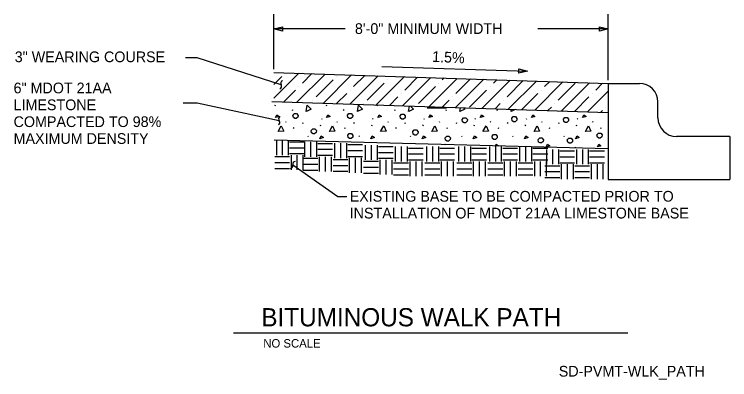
# Model space of a CAD drawing. Extents: x 9960.2 to 10030.1, y 10022.5 to 10058.1.
import ezdxf

# ---------------------------------------------------------------- set-up
doc = ezdxf.new("R2010")
doc.units = 0
for name, color, linetype in [('Default', 7, 'Continuous'), ('G-ANNO-TEXT', 7, 'Continuous'), ('G-ANNO-TTXT', 7, 'Continuous'), ('G-DETL-LINE', 7, 'Continuous'), ('G-DETL-OTLN', 7, 'Continuous'), ('G-DETL-PATT', 7, 'Continuous')]:
    doc.layers.add(name, color=color, linetype=linetype)

msp = doc.modelspace()

# ---------------------------------------------------------------- linework, layer by layer
at = {"layer": 'Default'}
for p, q in [((9997.025, 10052.061), (9997.037, 10052.073)), ((9994.36, 10049.396), (9994.36, 10049.396)), ((10018.234, 10042.898), (10018.234, 10041.987))]:
    msp.add_line(p, q, dxfattribs=at)
at = {"layer": 'G-ANNO-TEXT'}
for p, q in [((9985.587, 10052.756), (9985.587, 10058.112)), ((10018.229, 10051.69), (10018.229, 10058.112)), ((9992.55, 10056.685), (9985.587, 10056.685)), ((10018.229, 10056.685), (10011.359, 10056.685)), ((9996.134, 10053.035), (10010.341, 10052.567)), ((10000.549, 10048.997), (10002.434, 10048.997)), ((9981.617, 10027.034), (10020.141, 10027.034))]:
    msp.add_line(p, q, dxfattribs=at)
for points in [[(9986.42, 10056.477), (9985.587, 10056.685), (9986.42, 10056.893)], [(10017.395, 10056.893), (10018.229, 10056.685), (10017.395, 10056.477)], [(10009.515, 10052.802), (10010.341, 10052.567), (10009.501, 10052.386)]]:
    msp.add_lwpolyline(points, close=True, dxfattribs=at)
at = {"layer": 'G-ANNO-TTXT'}
for points in [[(9986.284, 10051.242), (9978.077, 10053.871), (9976.928, 10053.871)], [(9986.101, 10047.728), (9978.069, 10049.437), (9976.728, 10049.437)], [(9987.428, 10043.427), (9991.831, 10040.338), (9992.69, 10040.338)]]:
    msp.add_lwpolyline(points, dxfattribs=at)
for centre, start, end in [((9986.497, 10051.393), 109.10802, 215.36823), ((9986.072, 10051.091), 289.10802, 35.36823), ((9986.297, 10047.899), 114.85482, 221.11503), ((9986.297, 10047.899), 114.85482, 221.11503), ((9985.904, 10047.556), 294.85482, 41.11503), ((9985.904, 10047.556), 294.85482, 41.11503), ((9987.676, 10043.507), 91.81446, 198.07466), ((9987.676, 10043.507), 91.81446, 198.07466), ((9987.181, 10043.346), 271.81446, 18.07466), ((9987.181, 10043.346), 271.81446, 18.07466)]:
    msp.add_arc(centre, 0.26, start, end, dxfattribs=at)
at = {"layer": 'G-DETL-LINE'}
for p, q in [((9985.58, 10052.451), (10018.234, 10051.375)), ((9985.39, 10049.603), (10018.234, 10048.522)), ((10018.234, 10044.992), (9985.592, 10045.849))]:
    msp.add_line(p, q, dxfattribs=at)
at = {"layer": 'G-DETL-OTLN'}
for p, q in [((10018.234, 10051.375), (10021.277, 10051.375)), ((10018.234, 10051.375), (10018.234, 10046.843)), ((10023.086, 10048.005), (10023.086, 10049.566)), ((10018.234, 10046.843), (10018.234, 10041.986)), ((10030.097, 10046.196), (10024.896, 10046.196)), ((10030.097, 10046.196), (10030.097, 10041.987)), ((10018.234, 10041.987), (10030.097, 10041.987))]:
    msp.add_line(p, q, dxfattribs=at)
for centre, start, end in [((10021.277, 10049.566), 0, 90), ((10024.896, 10048.005), 180, 270)]:
    msp.add_arc(centre, 1.809, start, end, dxfattribs=at)
at = {"layer": 'G-DETL-PATT'}
for p, q in [((9985.58, 10049.944), (9988.006, 10052.371)), ((9986.697, 10052.394), (9986.697, 10052.394)), ((9987.83, 10049.529), (9990.587, 10052.286)), ((9988.363, 10051.395), (9989.296, 10052.328)), ((9990.41, 10049.444), (9993.167, 10052.201)), ((9992.99, 10049.359), (9995.747, 10052.116)), ((9993.36, 10051.062), (9994.457, 10052.158)), ((9985.58, 10051.277), (9986.364, 10052.061)), ((9989.696, 10050.062), (9991.361, 10051.728)), ((9991.694, 10052.061), (9991.694, 10052.061)), ((9994.693, 10049.729), (9996.359, 10051.395)), ((9995.571, 10049.274), (9998.327, 10052.031)), ((9996.692, 10051.728), (9996.692, 10051.728)), ((9998.151, 10049.189), (10000.908, 10051.946)), ((9998.358, 10050.728), (9999.618, 10051.988)), ((10000.731, 10049.104), (10003.488, 10051.861)), ((10001.689, 10051.395), (10001.689, 10051.395)), ((10002.022, 10051.728), (10002.198, 10051.903)), ((10003.312, 10049.019), (10006.068, 10051.776)), ((10003.355, 10050.395), (10004.778, 10051.818)), ((10005.892, 10048.934), (10008.649, 10051.691)), ((10007.02, 10051.395), (10007.358, 10051.733)), ((10008.352, 10050.062), (10009.939, 10051.648)), ((10008.472, 10048.849), (10011.229, 10051.606)), ((10011.052, 10048.764), (10013.809, 10051.521)), ((10012.017, 10051.062), (10012.519, 10051.563)), ((10013.35, 10049.729), (10015.015, 10051.395)), ((10013.633, 10048.679), (10016.389, 10051.436)), ((10017.014, 10050.728), (10017.68, 10051.393)), ((9986.54, 10049.572), (9987.697, 10050.728)), ((9988.03, 10051.062), (9988.03, 10051.062)), ((9993.027, 10050.728), (9993.027, 10050.728)), ((9999.69, 10049.396), (10001.356, 10051.062)), ((10004.688, 10049.063), (10006.353, 10050.728)), ((10006.686, 10051.062), (10006.686, 10051.062)), ((10011.684, 10050.728), (10011.684, 10050.728)), ((9991.7, 10049.402), (9992.694, 10050.395)), ((9996.861, 10049.232), (9997.691, 10050.062)), ((9998.024, 10050.395), (9998.024, 10050.395)), ((10003.022, 10050.062), (10003.022, 10050.062)), ((10009.762, 10048.807), (10011.351, 10050.395)), ((10014.923, 10048.637), (10016.348, 10050.062)), ((10016.213, 10048.594), (10018.234, 10050.615)), ((10016.681, 10050.395), (10016.681, 10050.395)), ((9985.702, 10049.197), (9985.747, 10049.297)), ((9989.362, 10049.729), (9989.362, 10049.729)), ((9990.702, 10049.197), (9990.747, 10049.297)), ((10002.021, 10049.062), (10002.689, 10049.729)), ((10007.182, 10048.892), (10007.686, 10049.396)), ((10008.019, 10049.729), (10008.019, 10049.729)), ((10013.016, 10049.396), (10013.016, 10049.396)), ((9987.389, 10048.741), (9987.434, 10048.841)), ((9992.389, 10048.741), (9992.434, 10048.841)), ((9995.702, 10049.197), (9995.731, 10049.263)), ((9997.389, 10048.741), (9997.434, 10048.841)), ((10002.389, 10048.741), (10002.434, 10048.841)), ((10007.389, 10048.741), (10007.434, 10048.841)), ((10012.343, 10048.722), (10012.683, 10049.063)), ((10017.503, 10048.552), (10017.681, 10048.729)), ((10018.014, 10049.063), (10018.014, 10049.063)), ((9990.215, 10047.954), (9990.26, 10047.887)), ((9995.215, 10047.954), (9995.26, 10047.887)), ((10000.215, 10047.954), (10000.26, 10047.887)), ((10005.215, 10047.954), (10005.26, 10047.887)), ((10010.215, 10047.954), (10010.26, 10047.887)), ((10015.215, 10047.954), (10015.26, 10047.887)), ((9986.71, 10047.671), (9986.755, 10047.605)), ((9988.399, 10047.454), (9988.444, 10047.554)), ((9990.131, 10047.222), (9990.176, 10047.322)), ((9991.71, 10047.671), (9991.755, 10047.605)), ((9993.399, 10047.454), (9993.444, 10047.554)), ((9995.131, 10047.222), (9995.176, 10047.322)), ((9996.71, 10047.671), (9996.755, 10047.605)), ((9998.399, 10047.454), (9998.444, 10047.554)), ((10000.131, 10047.222), (10000.176, 10047.322)), ((10001.71, 10047.671), (10001.755, 10047.605)), ((10003.399, 10047.454), (10003.444, 10047.554)), ((10005.131, 10047.222), (10005.176, 10047.322)), ((10006.71, 10047.671), (10006.755, 10047.605)), ((10008.399, 10047.454), (10008.444, 10047.554)), ((10010.131, 10047.222), (10010.176, 10047.322)), ((10011.71, 10047.671), (10011.755, 10047.605)), ((10013.399, 10047.454), (10013.444, 10047.554)), ((10015.131, 10047.222), (10015.176, 10047.322)), ((10016.71, 10047.671), (10016.755, 10047.605)), ((9987.5, 10046.967), (9987.545, 10047.067)), ((9992.5, 10046.967), (9992.545, 10047.067)), ((9997.5, 10046.967), (9997.545, 10047.067)), ((10002.5, 10046.967), (10002.545, 10047.067)), ((10007.5, 10046.967), (10007.545, 10047.067)), ((10012.5, 10046.967), (10012.545, 10047.067)), ((10017.5, 10046.967), (10017.545, 10047.067)), ((9985.817, 10045.813), (9985.817, 10044.365)), ((9986.396, 10045.813), (9986.396, 10044.365)), ((9986.975, 10045.813), (9986.975, 10044.365)), ((9988.888, 10046.256), (9988.932, 10046.19)), ((9993.888, 10046.256), (9993.932, 10046.19)), ((9998.888, 10046.256), (9998.932, 10046.19)), ((10003.888, 10046.256), (10003.932, 10046.19)), ((10008.888, 10046.256), (10008.932, 10046.19)), ((10013.888, 10046.256), (10013.932, 10046.19)), ((9987.109, 10045.678), (9988.557, 10045.678)), ((9987.109, 10045.099), (9988.557, 10045.099)), ((9988.575, 10045.659), (9988.575, 10044.211)), ((9989.154, 10045.659), (9989.154, 10044.211)), ((9989.733, 10045.659), (9989.733, 10044.211)), ((9989.867, 10045.524), (9991.315, 10045.524)), ((9991.508, 10045.535), (9991.508, 10044.087)), ((9992.087, 10045.535), (9992.087, 10044.087)), ((9992.666, 10045.535), (9992.666, 10044.087)), ((9992.8, 10045.4), (9994.248, 10045.4)), ((9994.501, 10045.357), (9994.501, 10043.909)), ((9995.08, 10045.357), (9995.08, 10043.909)), ((9995.659, 10045.357), (9995.659, 10043.909)), ((9995.793, 10045.222), (9997.241, 10045.222)), ((9997.422, 10045.202), (9997.422, 10043.755)), ((9998.001, 10045.202), (9998.001, 10043.755)), ((9998.58, 10045.202), (9998.58, 10043.755)), ((10000.483, 10045.202), (10000.483, 10043.755)), ((10001.062, 10045.202), (10001.062, 10043.755)), ((10001.641, 10045.202), (10001.641, 10043.755)), ((10003.617, 10045.202), (10003.617, 10043.755)), ((10004.196, 10045.202), (10004.196, 10043.755)), ((10004.775, 10045.202), (10004.775, 10043.755)), ((10006.631, 10045.202), (10006.631, 10043.755)), ((10007.211, 10045.202), (10007.211, 10043.755)), ((10007.79, 10045.202), (10007.79, 10043.755)), ((10009.58, 10045.202), (10009.58, 10043.755)), ((10010.159, 10045.202), (10010.159, 10043.755)), ((10010.738, 10045.202), (10010.738, 10043.755)), ((10015.01, 10045.192), (10015.021, 10045.092)), ((9987.109, 10044.52), (9988.557, 10044.52)), ((9989.867, 10044.945), (9991.315, 10044.945)), ((9992.8, 10044.821), (9994.248, 10044.821)), ((9995.793, 10044.643), (9997.241, 10044.643)), ((9998.714, 10045.068), (10000.162, 10045.068)), ((9998.714, 10044.489), (10000.162, 10044.489)), ((10001.775, 10045.068), (10003.223, 10045.068)), ((10001.775, 10044.489), (10003.223, 10044.489)), ((10004.909, 10045.068), (10006.357, 10045.068)), ((10004.909, 10044.489), (10006.357, 10044.489)), ((10007.924, 10045.068), (10009.371, 10045.068)), ((10007.924, 10044.489), (10009.371, 10044.489)), ((10010.872, 10045.068), (10012.32, 10045.068)), ((10010.872, 10044.489), (10012.32, 10044.489)), ((10012.204, 10044.928), (10012.204, 10043.48)), ((10012.783, 10044.928), (10012.783, 10043.48)), ((10013.362, 10044.928), (10013.362, 10043.48)), ((10013.496, 10044.793), (10014.944, 10044.793)), ((10015.126, 10044.928), (10015.126, 10043.48)), ((10015.705, 10044.928), (10015.705, 10043.48)), ((10016.284, 10044.928), (10016.284, 10043.48)), ((10016.418, 10044.793), (10017.866, 10044.793)), ((9985.661, 10044.23), (9987.109, 10044.23)), ((9987.254, 10044.375), (9987.254, 10042.927)), ((9987.833, 10044.375), (9987.833, 10042.927)), ((9988.412, 10044.375), (9988.412, 10042.927)), ((9988.42, 10044.076), (9989.867, 10044.076)), ((9989.867, 10044.366), (9991.315, 10044.366)), ((9990.012, 10044.221), (9990.012, 10042.773)), ((9990.591, 10044.221), (9990.591, 10042.773)), ((9991.17, 10044.221), (9991.17, 10042.773)), ((9991.352, 10043.953), (9992.8, 10043.953)), ((9992.8, 10044.242), (9994.248, 10044.242)), ((9992.945, 10044.097), (9992.945, 10042.65)), ((9993.524, 10044.097), (9993.524, 10042.65)), ((9994.103, 10044.097), (9994.103, 10042.65)), ((9994.345, 10043.775), (9995.793, 10043.775)), ((9995.793, 10044.064), (9997.241, 10044.064)), ((9995.938, 10043.92), (9995.938, 10042.472)), ((9996.517, 10043.92), (9996.517, 10042.472)), ((9997.096, 10043.92), (9997.096, 10042.472)), ((9998.714, 10043.91), (10000.162, 10043.91)), ((9998.859, 10043.765), (9998.859, 10042.317)), ((9999.438, 10043.765), (9999.438, 10042.317)), ((10000.017, 10043.765), (10000.017, 10042.317)), ((10001.775, 10043.91), (10003.223, 10043.91)), ((10001.92, 10043.765), (10001.92, 10042.317)), ((10002.499, 10043.765), (10002.499, 10042.317)), ((10003.078, 10043.765), (10003.078, 10042.317)), ((10004.909, 10043.91), (10006.357, 10043.91)), ((10005.054, 10043.765), (10005.054, 10042.317)), ((10005.633, 10043.765), (10005.633, 10042.317)), ((10006.212, 10043.765), (10006.212, 10042.317)), ((10007.924, 10043.91), (10009.371, 10043.91)), ((10008.069, 10043.765), (10008.069, 10042.317)), ((10008.648, 10043.765), (10008.648, 10042.317)), ((10009.227, 10043.765), (10009.227, 10042.317)), ((10010.872, 10043.91), (10012.32, 10043.91)), ((10011.017, 10043.765), (10011.017, 10042.317)), ((10011.596, 10043.765), (10011.596, 10042.317)), ((10012.175, 10043.765), (10012.175, 10042.317)), ((10013.496, 10044.214), (10014.944, 10044.214)), ((10016.418, 10044.214), (10017.866, 10044.214)), ((9985.661, 10043.651), (9987.109, 10043.651)), ((9985.661, 10043.072), (9987.109, 10043.072)), ((9988.42, 10043.497), (9989.867, 10043.497)), ((9991.352, 10043.374), (9992.8, 10043.374)), ((9994.345, 10043.196), (9995.793, 10043.196)), ((9997.267, 10043.62), (9998.714, 10043.62)), ((9997.267, 10043.041), (9998.714, 10043.041)), ((10000.327, 10043.62), (10001.775, 10043.62)), ((10000.327, 10043.041), (10001.775, 10043.041)), ((10003.462, 10043.62), (10004.909, 10043.62)), ((10003.462, 10043.041), (10004.909, 10043.041)), ((10006.476, 10043.62), (10007.924, 10043.62)), ((10006.476, 10043.041), (10007.924, 10043.041)), ((10009.425, 10043.62), (10010.872, 10043.62)), ((10009.425, 10043.041), (10010.872, 10043.041)), ((10012.049, 10043.346), (10013.496, 10043.346)), ((10013.496, 10043.635), (10014.944, 10043.635)), ((10013.641, 10043.49), (10013.641, 10042.043)), ((10014.22, 10043.49), (10014.22, 10042.043)), ((10014.799, 10043.49), (10014.799, 10042.043)), ((10014.97, 10043.346), (10016.418, 10043.346)), ((10016.418, 10043.635), (10017.866, 10043.635)), ((10016.563, 10043.49), (10016.563, 10042.043)), ((10017.142, 10043.49), (10017.142, 10042.043)), ((10017.721, 10043.49), (10017.721, 10042.043)), ((9988.42, 10042.918), (9989.867, 10042.918)), ((9991.352, 10042.794), (9992.8, 10042.794)), ((9994.345, 10042.617), (9995.793, 10042.617)), ((9997.267, 10042.462), (9998.714, 10042.462)), ((10000.327, 10042.462), (10001.775, 10042.462)), ((10003.462, 10042.462), (10004.909, 10042.462)), ((10006.476, 10042.462), (10007.924, 10042.462)), ((10009.425, 10042.462), (10010.872, 10042.462)), ((10012.049, 10042.766), (10013.496, 10042.766)), ((10014.97, 10042.766), (10016.418, 10042.766)), ((10012.049, 10042.187), (10013.496, 10042.187)), ((10014.97, 10042.187), (10016.418, 10042.187))]:
    msp.add_line(p, q, dxfattribs=at)
for points in [[(9988.74, 10048.627), (9988.828, 10049.261), (9989.225, 10048.851), (9988.75, 10048.63)], [(9993.74, 10048.627), (9993.828, 10049.261), (9994.225, 10048.851), (9993.75, 10048.63)], [(9998.74, 10048.627), (9998.814, 10049.161)], [(9998.928, 10049.157), (9999.225, 10048.851), (9998.75, 10048.63)], [(10003.74, 10048.627), (10003.791, 10048.997)], [(10004.093, 10048.987), (10004.225, 10048.851), (10003.75, 10048.63)], [(10008.74, 10048.627), (10008.768, 10048.833)], [(10009.16, 10048.82), (10008.75, 10048.63)], [(10013.74, 10048.627), (10013.746, 10048.669)], [(10013.828, 10048.667), (10013.75, 10048.63)], [(9985.724, 10048.031), (9985.858, 10048.309), (9986.08, 10048.142), (9985.724, 10048.031)], [(9987.477, 10048.03), (9987.436, 10048.266), (9987.582, 10048.43), (9987.802, 10048.426), (9987.943, 10048.254), (9987.927, 10048.078), (9987.763, 10047.935), (9987.621, 10047.933), (9987.477, 10048.03)], [(9990.724, 10048.031), (9990.858, 10048.309), (9991.08, 10048.142), (9990.724, 10048.031)], [(9992.806, 10048.03), (9992.765, 10048.266), (9992.911, 10048.43), (9993.131, 10048.426), (9993.273, 10048.254), (9993.257, 10048.078), (9993.092, 10047.935), (9992.95, 10047.933), (9992.806, 10048.03)], [(9995.724, 10048.031), (9995.858, 10048.309), (9996.08, 10048.142), (9995.724, 10048.031)], [(9997.946, 10047.976), (9997.905, 10048.212), (9998.051, 10048.376), (9998.271, 10048.372), (9998.413, 10048.199), (9998.396, 10048.023), (9998.232, 10047.881), (9998.09, 10047.879), (9997.946, 10047.976)], [(10000.724, 10048.031), (10000.858, 10048.309), (10001.08, 10048.142), (10000.724, 10048.031)], [(10004.005, 10047.624), (10003.964, 10047.86), (10004.111, 10048.024), (10004.331, 10048.02), (10004.472, 10047.848), (10004.456, 10047.672), (10004.292, 10047.529), (10004.149, 10047.527), (10004.005, 10047.624)], [(10005.724, 10048.031), (10005.858, 10048.309), (10006.08, 10048.142), (10005.724, 10048.031)], [(10008.848, 10047.732), (10008.807, 10047.968), (10008.953, 10048.132), (10009.173, 10048.128), (10009.315, 10047.956), (10009.298, 10047.78), (10009.134, 10047.638), (10008.992, 10047.635), (10008.848, 10047.732)], [(10010.724, 10048.031), (10010.858, 10048.309), (10011.08, 10048.142), (10010.724, 10048.031)], [(10013.9, 10047.658), (10013.859, 10047.894), (10014.005, 10048.058), (10014.225, 10048.054), (10014.366, 10047.881), (10014.35, 10047.705), (10014.186, 10047.563), (10014.043, 10047.561), (10013.9, 10047.658)], [(10015.724, 10048.031), (10015.858, 10048.309), (10016.08, 10048.142), (10015.724, 10048.031)], [(9986.002, 10046.667), (9986.302, 10047.233), (9986.535, 10046.712), (9986.013, 10046.667)], [(9991.002, 10046.667), (9991.302, 10047.233), (9991.535, 10046.712), (9991.013, 10046.667)], [(9996.002, 10046.667), (9996.302, 10047.233), (9996.535, 10046.712), (9996.013, 10046.667)], [(10001.002, 10046.667), (10001.302, 10047.233), (10001.535, 10046.712), (10001.013, 10046.667)], [(10006.002, 10046.667), (10006.302, 10047.233), (10006.535, 10046.712), (10006.013, 10046.667)], [(10011.002, 10046.667), (10011.302, 10047.233), (10011.535, 10046.712), (10011.013, 10046.667)], [(10016.002, 10046.667), (10016.302, 10047.233), (10016.535, 10046.712), (10016.013, 10046.667)], [(9989.262, 10046.541), (9989.221, 10046.777), (9989.367, 10046.941), (9989.588, 10046.937), (9989.729, 10046.765), (9989.713, 10046.589), (9989.548, 10046.447), (9989.406, 10046.445), (9989.262, 10046.541)], [(9992.833, 10046.081), (9992.792, 10046.317), (9992.938, 10046.481), (9993.158, 10046.477), (9993.3, 10046.305), (9993.284, 10046.129), (9993.119, 10045.987), (9992.977, 10045.984), (9992.833, 10046.081)], [(9999.19, 10046.433), (9999.149, 10046.669), (9999.295, 10046.833), (9999.516, 10046.829), (9999.657, 10046.657), (9999.641, 10046.481), (9999.476, 10046.338), (9999.334, 10046.336), (9999.19, 10046.433)], [(10017.173, 10046.115), (10017.132, 10046.351), (10017.278, 10046.515), (10017.498, 10046.511), (10017.64, 10046.339), (10017.624, 10046.163), (10017.459, 10046.02), (10017.317, 10046.018), (10017.173, 10046.115)], [(9990.053, 10045.968), (9990.187, 10046.245), (9990.409, 10046.079), (9990.053, 10045.968)], [(9995.053, 10045.968), (9995.187, 10046.245), (9995.409, 10046.079), (9995.053, 10045.968)], [(10000.053, 10045.968), (10000.187, 10046.245), (10000.409, 10046.079), (10000.053, 10045.968)], [(10002.355, 10045.838), (10002.314, 10046.074), (10002.461, 10046.238), (10002.681, 10046.234), (10002.822, 10046.061), (10002.806, 10045.885), (10002.641, 10045.743), (10002.499, 10045.741), (10002.355, 10045.838)], [(10005.053, 10045.968), (10005.187, 10046.245), (10005.409, 10046.079), (10005.053, 10045.968)], [(10006.927, 10046), (10006.886, 10046.236), (10007.032, 10046.4), (10007.253, 10046.396), (10007.394, 10046.224), (10007.378, 10046.048), (10007.213, 10045.905), (10007.071, 10045.903), (10006.927, 10046)], [(10010.053, 10045.968), (10010.187, 10046.245), (10010.409, 10046.079), (10010.053, 10045.968)], [(10011.438, 10045.655), (10011.397, 10045.891), (10011.543, 10046.055), (10011.763, 10046.051), (10011.905, 10045.879), (10011.889, 10045.703), (10011.724, 10045.56), (10011.582, 10045.558), (10011.438, 10045.655)], [(10014.278, 10045.628), (10014.237, 10045.864), (10014.384, 10046.028), (10014.604, 10046.024), (10014.745, 10045.852), (10014.729, 10045.676), (10014.565, 10045.533), (10014.422, 10045.531), (10014.278, 10045.628)], [(10015.053, 10045.968), (10015.187, 10046.245), (10015.409, 10046.079), (10015.053, 10045.968)], [(10002.283, 10045.411), (10002.303, 10045.452), (10002.36, 10045.409)], [(10007.221, 10045.281), (10007.303, 10045.452), (10007.525, 10045.285), (10007.488, 10045.274)], [(10012.17, 10045.174), (10012.303, 10045.452), (10012.525, 10045.285), (10012.17, 10045.174)], [(10017.17, 10045.174), (10017.303, 10045.452), (10017.525, 10045.285), (10017.17, 10045.174)]]:
    msp.add_lwpolyline(points, dxfattribs=at)

# ---------------------------------------------------------------- texts
at = {"layer": 'G-ANNO-TEXT'}
for s, height, p in [('8\'-0" MINIMUM WIDTH', 1.044, (9993.492, 10056.197)), ('3" WEARING COURSE', 1.044, (9960.265, 10053.443)), ('6" MDOT 21AA ', 1.044, (9960.152, 10050.404)), ('LIMESTONE ', 1.044, (9960.152, 10048.76)), ('COMPACTED TO 98% ', 1.044, (9960.152, 10047.116)), ('MAXIMUM DENSITY', 1.044, (9960.152, 10045.472)), ('EXISTING BASE TO BE COMPACTED PRIOR TO', 1.044, (9992.98, 10039.838)), ('INSTALLATION OF MDOT 21AA LIMESTONE BASE', 1.044, (9992.98, 10038.194)), ('BITUMINOUS WALK PATH', 1.776, (9984.348, 10027.671)), ('NO SCALE', 0.828, (9984.542, 10025.599)), ('SD-PVMT-WLK_PATH', 1.044, (10013.402, 10022.77))]:
    msp.add_text(s, height=height, dxfattribs=at).set_placement(p)
msp.add_text('1.5%', height=1.044, rotation=357.1624, dxfattribs=at).set_placement((10001.013, 10053.484))

doc.saveas('drawing.dxf')
